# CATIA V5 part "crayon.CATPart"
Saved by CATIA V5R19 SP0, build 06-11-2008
Part number: crayon
Publications: "Longueur_fourche_1", "Longueur_fourche_2"
Bounding box of the stored display mesh (mm): x 0 to 12, y 13.381 to 77.834, z -32.132 to 118.342
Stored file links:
  H:\EU_thinkMotion\IAO_2010\iao\IAO_MMS_Groupe3\PB\jpeguet\jpeguet_IAO\jpeguet_IAO\crayon.CATPart
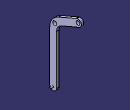
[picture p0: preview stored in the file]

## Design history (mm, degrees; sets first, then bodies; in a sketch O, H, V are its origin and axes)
Parameters
  dent_fourche = 20 mm
  Longueur_fourche_1 = 30 mm
  Longueur_fourche_2 = 40 mm
Body1 (main body)
  Sketch1 on yz-plane, origin (0, 0, 0), H (0, 1, 0), V (0, 0, 1)
    point P1 (13.3813, -25.3072)
    line L1 (13.3813, -25.3072) -> (13.3813, 74.6928)
    arc A1 centre (43.1298, 74.6928) radius 29.7484 from (13.3813, 74.6928) to (31.421, 102.0401) cw
    point P3 (43.1298, 74.6928)
    line L2 (31.421, 102.0401) -> (68.1924, 117.7838)
    arc A2 centre (70.9476, 111.3488) radius 7 from (68.1924, 117.7838) to (73.7027, 104.9139) cw
    line L3 (27.3813, 74.6928) -> (27.3813, -25.3072)
    arc A3 centre (43.1298, 74.6928) radius 15.7484 from (36.9313, 89.1701) to (27.3813, 74.6928) ccw
    point P11 (43.1298, 74.6928)
    line L4 (36.9313, 89.1701) -> (73.7027, 104.9139)
    arc A4 centre (20.3813, -25.3072) radius 7 from (13.3813, -25.3072) to (27.3813, -25.3072) ccw
    point P13 (13.3813, -25.3072)
    length L4 = 40 {= Longueur_fourche_2}
    length L3 = 100
    length L1 = 100
    tangency: A1 L1, A2 L2, A3 L3, A1 L2, L4 A3, L4 A2, L3 A4
    vertical: L1 V, L3 V
    coincidence: P3 P11, P13 P1
    parallelism: L4 L2
  Pad1: profile Sketch1, direction (1, 0, 0), length 5
  Fillet1: radius 2, on edge [face of Pad1 | face of Pad1] (x4), deactivated
  Sketch2 on end face of Pad1, origin (5, 20.3108, 84.8108), H (0, 1, 0), V (0, 0, 1)
    point P1 (3.4319, 2.7199)
    construction line L1 (-15.2723, -1.681) -> (43.6442, 23.5441)
    reference projected line E1 (45.1352, 31.7972) -> (8.3638, 16.0534) from edge [face of Pad1 from Sketch1.L2 | end face of Pad1]
    reference projected line E2 (45.1352, 31.7972) -> (8.3638, 16.0534) from edge [face of Pad1 from Sketch1.L2 | end face of Pad1]
    construction line L2 (0.0705, -33.4067) -> (0.0705, 10.0355)
    reference projected line E3 (7.0705, -39.8108) -> (7.0705, -9.8108) from edge [face of Pad1 from Sketch1.L3 | end face of Pad1]
    construction line L3 (6.8065, -28.4747) -> (6.8065, 12.6338)
    construction line L4 (32.2526, 11.467) -> (-14.0141, -8.3421)
    construction line L5 (0.0705, 4.8881) -> (6.8065, 0.5722)
    point P10 (0.0705, 4.8881)
    point P11 (6.8065, 0.5722)
    distance L1 E2 = 7
    distance L2 E3 = 7
    distance P11 P1 = 4
    distance P1 P10 = 4
    parallelism: L1 E1, L4 L1
    vertical: L2 V, L3 V
    coincidence: P10 L2, P10 L1, P11 L4, P11 L3
  Hole1: placed by Sketch2, at (5, 23.7427, 87.5307) direction (-1, 0, 0), diameter 8, through (limit type 3)
  Sketch3 on end face of Pad1, origin (5, 67.5979, 110.077), H (0, 1, 0), V (0, 0, 1)
    point P1 (3.3497, 1.2719)
    reference projected arc E1 centre (3.3497, 1.2719) radius 7 from (6.1048, -5.1631) to (0.5945, 7.7069) ccw from edge [face of Pad1 from Sketch1.A2 | end face of Pad1]
    concentricity: E1 P1
  Hole2: placed by Sketch3, at (5, 70.9476, 111.3488) direction (-1, 0, 0), diameter 8, through (limit type 3)
  Sketch4 on end face of Pad1, origin (5, 0, 0), H (0, 1, 0), V (0, 0, 1)
    circle A1 centre (20.3813, -25.3072) radius 1.5
    point P1 (20.3813, -25.3072)
    reference projected arc E1 centre (20.3813, -25.3072) radius 7 from (13.3813, -25.3072) to (27.3813, -25.3072) ccw from edge [face of Pad1 from Sketch1.A4 | end face of Pad1]
    radius A1 = 1.5
    concentricity: P1 E1
  Pad2: profile Sketch4, direction (1, 0, 0), length 7
  Chamfer1: length 1.3, angle 45, on end face of Pad2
